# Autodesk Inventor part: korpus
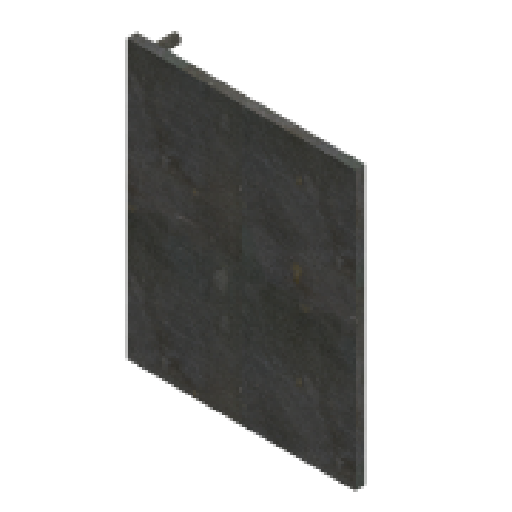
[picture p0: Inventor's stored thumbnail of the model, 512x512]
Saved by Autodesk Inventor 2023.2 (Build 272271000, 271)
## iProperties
Created: 2022-12
Part Number: korpus
Material: Stal
Document SubType Name: Modeling
Designer: TEST
Density: 7.85 g/cm^3
Appearance: Płyta
Author: TEST
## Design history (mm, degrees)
sketch "Szkic1"
  geometry: L1 (115, -140)-(-115, -140); L2 (-115, -140)-(-115, 140); L3 (-115, 140)-(115, 140); L4 (115, 140)-(115, -140); L5 (115, -140)-(-115, 140); L6 (-115, -140)-(115, 140); 1 further point
  constraints: 12 end point, 2 midpoint, 2 parallel, 1 horizontal, 1 perpendicular
  dimensions: "d0" = 230 distance of L2.end L3.end; "d1" = 280 distance of L1.end L2.end
extrude "Wyciągnięcie proste1" new body sketch "Szkic1" distance "d2" = 10; taper "d3" = 0 deg
sketch "Szkic2"
  geometry: C1 r 15 at (0, 0) reference; C2 r 5 at (100.596, 107.185) reference; 1 further point
  node "Odniesienie1"
  node "Odniesienie2"
node "Płaszczyzna konstrukcyjna1"
extrude "Wyciągnięcie proste2" join sketch "Szkic2" stored distance "d4" = 10; taper "d5" = 0 deg
chamfer "Faza1" distance "d6" = 0.5; stored, may be unused: second distance "d7" = 2, angle "d8" = 45 deg
sketch "Szkic3"
  geometry: L1 (-115, 140)-(115, 140) reference; L2 (115, 140)-(115, -140) reference; C1 r 5 at (95, 135); 1 further point
  constraints: 1 centre point, 1 tangent
  dimensions: "d9" = 10 diameter of C1; "d10" = 20 distance from line of L2 C1.centre
extrude "Wyciągnięcie proste3" join sketch "Szkic3" stored distance "d11" = 10; taper "d12" = 0 deg
node "Bryła1"
